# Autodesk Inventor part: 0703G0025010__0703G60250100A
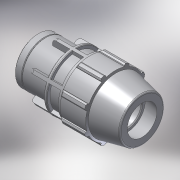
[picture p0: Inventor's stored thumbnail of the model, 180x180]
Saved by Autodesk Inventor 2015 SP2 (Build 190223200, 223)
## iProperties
Created: 2017-02
Part Number: 0703G0025010__0703G60250100A
Material: PVC-Piping
Description: PLASSON FEMALE ADAPTOR G 25-1"
Document SubType Name: Modeling
Designer: KIM
Mass: 92.6774 g
Surface Area: 199.44 cm^2
Volume: 66.1981 cm^3
Density: 1.4 g/cm^3
Appearance: Smooth - White
Author: KIM
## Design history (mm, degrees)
derived "0703G0.ipt"
feature "Solid1::0703G0.ipt"
tag "TaggingFeature1"
body "Solid1"
other parameters: "d2" = 25, "d4" = 12.57143, "d5" = 22, "d7" = 54, "d9" = 12.57143, "d11" = 2.51429, "d12" = 43.2, "d13" = 120 deg, "d14" = 37.5, "d15" = 12 deg, "d16" = 48.6, "d18" = 1.25, "d19" = 35 deg, "d20" = 17.5 deg, "d21" = 50.22, "d23" = 0, "d25" = 360 deg, "d27" = 1.08, "d34" = 2.7, "d35" = 26.4, "d36" = 0, "d42" = 22, "d43" = 1.62, "d46" = 0.75, "d49" = 63, "d51" = 88, "d53" = 0.5, "d55" = 360 deg, "d61" = 14, "d63" = 30.291, "d64" = 29.33333, "d65" = 2.7, "d66" = 0.5, "d67" = 1, "d68" = 7, "d69" = 38.88, "d_" = 25, "E_" = 54, "H_" = 88, "l_" = 63, "l_2" = 14, "Rp_" = 30.291
